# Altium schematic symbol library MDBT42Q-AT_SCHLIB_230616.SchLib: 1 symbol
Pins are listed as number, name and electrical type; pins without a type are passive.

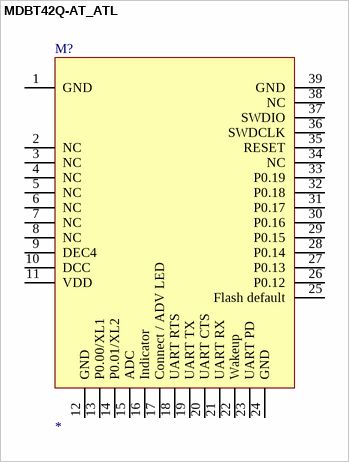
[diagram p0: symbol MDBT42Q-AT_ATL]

## MDBT42Q-AT_ATL
designator M?
MDBT42Q(52832_52810_52811)
pins: 1 GND, 2 NC, 3 NC, 4 NC, 5 NC, 6 NC, 7 NC, 8 NC, 9 DEC4, 10 DCC, 11 VDD, 12 GND, 13 P0.00/XL1, 14 P0.01/XL2, 15 ADC, 16 Indicator, 17 Connect / ADV LED, 18 UART RTS, 19 UART TX, 20 UART CTS, 21 UART RX, 22 Wakeup, 23 UART PD, 24 GND, 25 Flash default, 26 P0.12, 27 P0.13, 28 P0.14, 29 P0.15, 30 P0.16, 31 P0.17, 32 P0.18, 33 P0.19, 34 NC, 35 RESET, 36 SWDCLK, 37 SWDIO, 38 NC, 39 GND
